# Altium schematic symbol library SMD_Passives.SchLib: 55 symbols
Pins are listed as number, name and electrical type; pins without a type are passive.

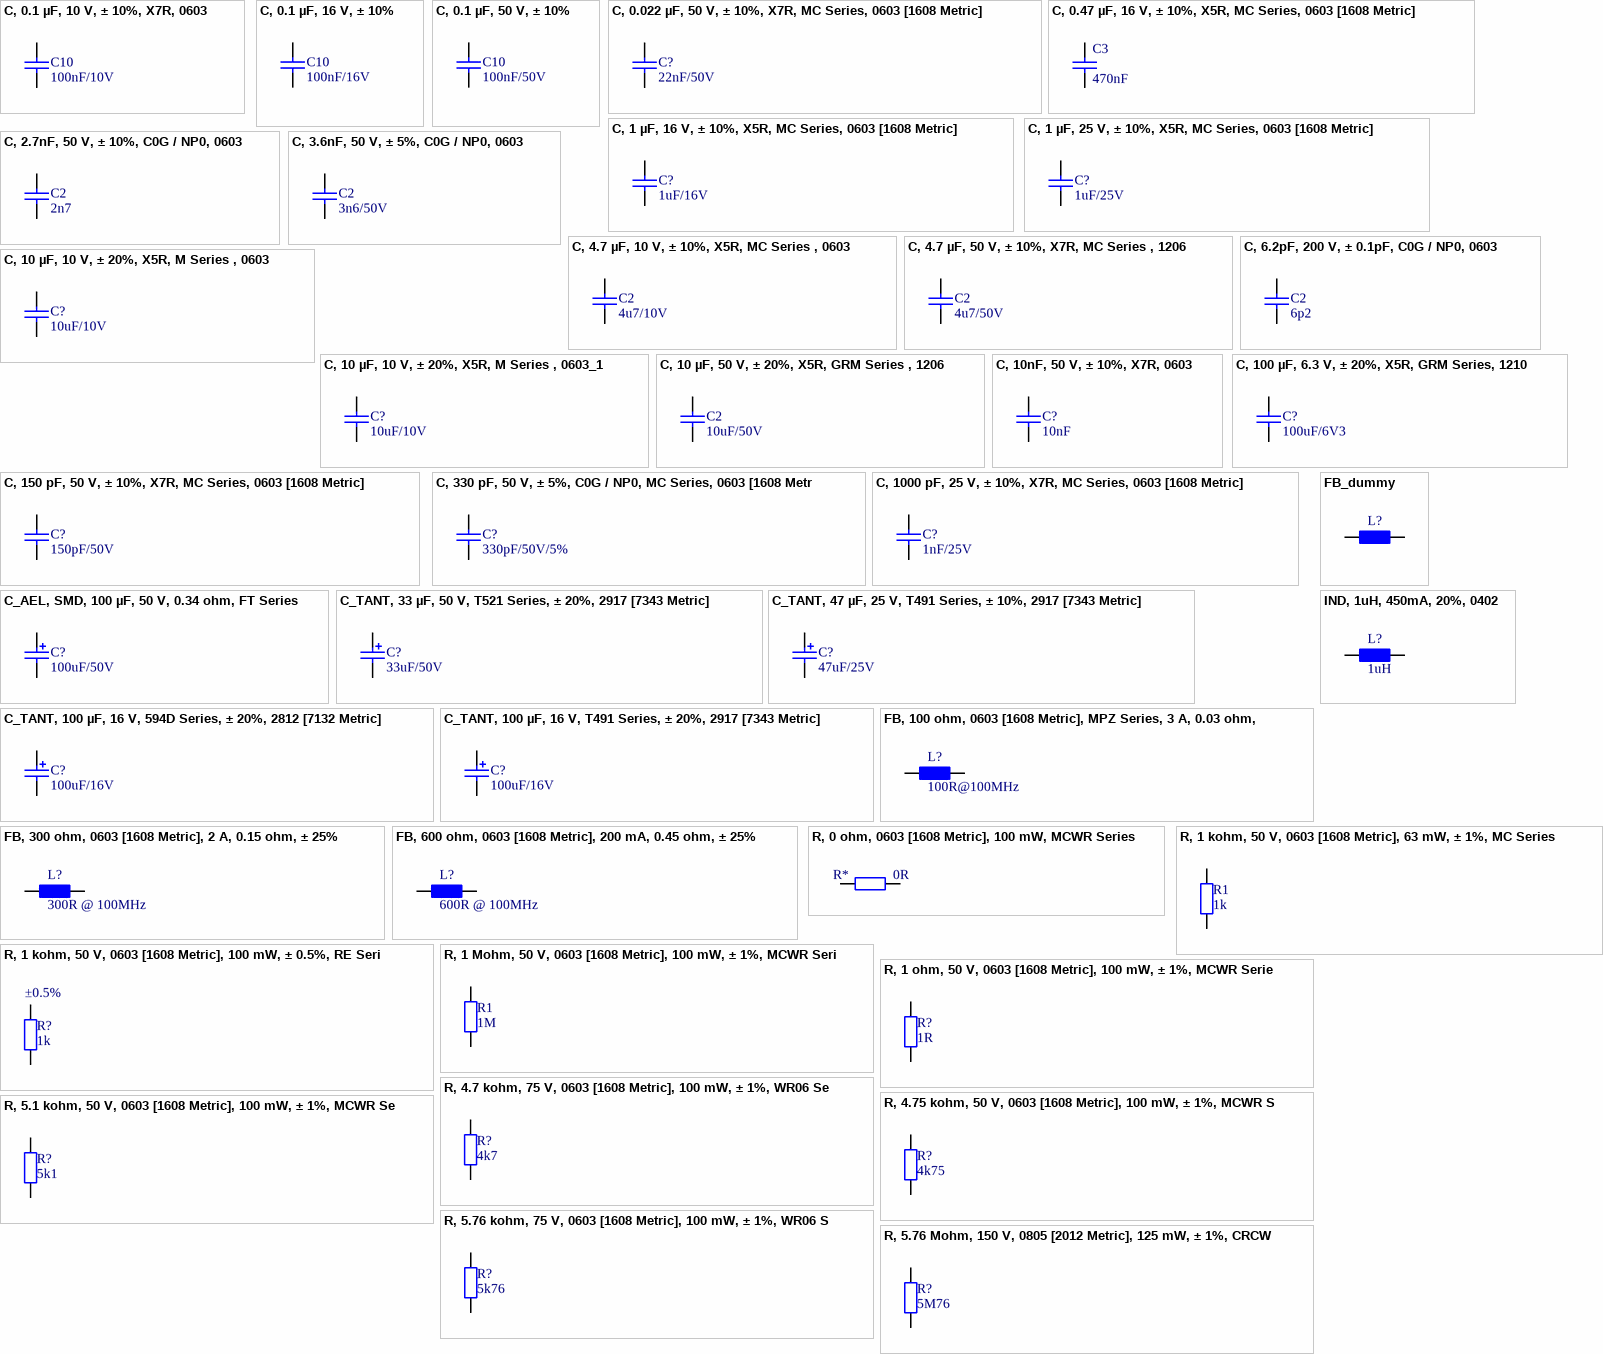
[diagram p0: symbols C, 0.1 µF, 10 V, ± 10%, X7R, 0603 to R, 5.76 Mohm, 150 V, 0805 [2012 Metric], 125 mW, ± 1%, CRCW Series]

## C, 0.1 µF, 10 V, ± 10%, X7R, 0603
designator C10, comment 100nF/10V
SMD Multilayer Ceramic Capacitor, 0603 [1608 Metric], 0.1 µF, 10 V, ± 10%, X7R, MC Series; MPN: MC0603B104K100CT; Type: MLCC; VoltageRating: 10V; MF: Multicomp; Capacitance: 100nF
footprint C0603 (0603 ceramic capacitor)
footprint C0603_BYPADD
footprint C0603_BYPASS
pins: 1, 2

## C, 0.1 µF, 16 V, ± 10%
designator C10, comment 100nF/16V
SMD Multilayer Ceramic Capacitor, 0603 [1608 Metric], 0.1 µF, 16 V, ± 10%, X7R, MC Series; MPN: MC0603B104K160CT; Type: MLCC; VoltageRating: 16V; ComponentLinknDescription: Datasheet; MF: Multicomp; Capacitance: 100nF
footprint C0603 (0603 ceramic capacitor)
footprint C0603_BYPADD
footprint C0603_BYPASS
pins: 1, 2

## C, 0.1 µF, 50 V, ± 10%
designator C10, comment 100nF/50V
SMD Multilayer Ceramic Capacitor, 0603 [1608 Metric], 0.1 µF, 50 V, ± 10%, X7R, MC Series; MPN: MC0603B104K500CT; Type: MLCC; VoltageRating: 50V; ComponentLinknDescription: Datasheet; MF: Multicomp; Capacitance: 100nF
footprint C0603 (0603 ceramic capacitor)
footprint C0603_BYPADD
footprint C0603_BYPASS
pins: 1, 2

## C, 0.022 µF, 50 V, ± 10%, X7R, MC Series, 0603 [1608 Metric]
designator C?, comment 22nF/50V
SMD Multilayer Ceramic Capacitor, 0603 [1608 Metric], 0.022 µF, 50 V, ± 10%, X7R, MC Series; MPN: MC0603B223K500CT; Type: MLCC; VoltageRating: 50V; MF: MULTICOMP; Capacitance: 22nF
footprint C0603 (0603 ceramic capacitor)
pins: 1, 2

## C, 0.47 µF, 16 V, ± 10%, X5R, MC Series, 0603 [1608 Metric]
designator C3, comment 470nF
SMD Multilayer Ceramic Capacitor, 0603 [1608 Metric], 0.47 µF, 16 V, ± 10%, X5R, MC Series; MPN: MC0603X474K160CT; Type: MLCC; Voltage rating: 16V; ComponentLinknDescription: Datasheet; MF: Multicomp
footprint C0603 (0603 ceramic capacitor)
pins: 1, 2

## C, 1 µF, 16 V, ± 10%, X5R, MC Series, 0603 [1608 Metric]
designator C?, comment 1uF/16V
SMD Multilayer Ceramic Capacitor, 0603 [1608 Metric], 1 µF, 16 V, ± 10%, X5R, MC Series; MPN: MC0603X105K160CT; Type: MLCC; VoltageRating: 16V; MF: MULTICOMP; Capacitance: 1uF
footprint C0603 (0603 ceramic capacitor)
pins: 1, 2

## C, 1 µF, 25 V, ± 10%, X5R, MC Series, 0603 [1608 Metric]
designator C?, comment 1uF/25V
SMD Multilayer Ceramic Capacitor, 0603 [1608 Metric], 1 µF, 25 V, ± 10%, X5R, MC Series; MPN: MC0603X105K250CT; Type: MLCC; VoltageRating: 25V; MF: MULTICOMP; Capacitance: 1uF
footprint C0603 (0603 ceramic capacitor)
pins: 1, 2

## C, 2.7nF, 50 V, ± 10%, C0G / NP0, 0603
designator C2, comment 2n7
SMD Multilayer Ceramic Capacitor, 0603 [1608 Metric], 2700 pF, 50 V, ± 10%, X7R, MC Series; MPN: MC0603B272K500CT; Type: MLCC; VoltageRating: 50V; MF: MULTICOMP
footprint C0603 (0603 ceramic capacitor)
pins: 1, 2

## C, 3.6nF, 50 V, ± 5%, C0G / NP0, 0603
designator C2, comment 3n6/50V
SMD Multilayer Ceramic Capacitor, 0603 [1608 Metric], 3600 pF, 50 V, ± 5%, C0G / NP0, C Series; MPN: C1608C0G1H151J080AA; Type: MLCC; VoltageRating: 50V; MF: TDK; Capacitance: 3n6
footprint C0603 (0603 ceramic capacitor)
pins: 1, 2

## C, 4.7 µF, 10 V, ± 10%, X5R, MC Series , 0603
designator C2, comment 4u7/10V
SMD Multilayer Ceramic Capacitor, 0603 [1608 Metric], 4.7 µF, 10 V, ± 10%, X5R, MC Series; MPN: MC0603X475K100CT; Type: MLCC; VoltageRating: 10V; MF: MULTICOMP; Capacitance: 4u7
footprint C0603 (Footprint not found)
pins: 1, 2

## C, 4.7 µF, 50 V, ± 10%, X7R, MC Series , 1206
designator C2, comment 4u7/50V
SMD Multilayer Ceramic Capacitor, 1206 [3216 Metric], 4.7 µF, 50 V, ± 10%, X7R, MC Series; MPN: MC1206B475K500CT; Type: MLCC; VoltageRating: 50V; MF: MULTICOMP; Capacitance: 4u7
footprint C1206 (1206 ceramic capacitor)
pins: 1, 2

## C, 6.2pF, 200 V, ± 0.1pF, C0G / NP0, 0603
designator C2, comment 6p2
Multilayer Ceramic Capacitors MLCC - SMD/SMT 200V 6.2pF C0G 0603 .1pF Tol; MPN: 06032U6R2BAT2A; Characteristic: C0G/NP0; MF: AVX; Precision: 0.1pF
footprint C0603 (0603 ceramic capacitor)
pins: 1, 2

## C, 10 µF, 10 V, ± 20%, X5R, M Series , 0603
designator C?, comment 10uF/10V
SMD Multilayer Ceramic Capacitor, 0603 [1608 Metric], 10 µF, 10 V, ± 20%, X5R, M Series; MPN: LMK107BBJ106MALT; Type: MLCC; VoltageRating: 10V; MF: TAIYO YUDEN; Capacitance: 10uF
footprint C0603 (0603 ceramic capacitor)
pins: 1, 2

## C, 10 µF, 10 V, ± 20%, X5R, M Series , 0603_1
designator C?, comment 10uF/10V
SMD Multilayer Ceramic Capacitor, 0603 [1608 Metric], 10 µF, 10 V, ± 20%, X5R, M Series; MPN: LMK107BBJ106MALT; Type: MLCC; VoltageRating: 10V; MF: TAIYO YUDEN; Capacitance: 10uF
footprint C0603 (0603 ceramic capacitor)
pins: 1, 2

## C, 10 µF, 50 V, ± 20%, X5R, GRM Series , 1206
designator C2, comment 10uF/50V
SMD Multilayer Ceramic Capacitor, 1206 [3216 Metric], 10 µF, 50 V, ± 20%, X5R, GRM Series; MPN: GRM31CR61H106MA12L; Type: MLCC; VoltageRating: 50V; MF: MURATA; Capacitance: 10uF
footprint C1206 (1206 ceramic capacitor)
pins: 1, 2

## C, 10nF, 50 V, ± 10%, X7R, 0603
designator C?, comment 10nF
SMD Multilayer Ceramic Capacitor, 0603 [1608 Metric], 0.01 µF, 50 V, ± 10%, X7R, MC Series; MPN: MC0603B103K500CT; Type: MLCC; VoltageRating: 50V; MF: MULTICOMP
footprint C0603 (0603 ceramic capacitor)
pins: 1, 2

## C, 100 µF, 6.3 V, ± 20%, X5R, GRM Series, 1210
designator C?, comment 100uF/6V3
SMD Multilayer Ceramic Capacitor, 1210 [3225 Metric], 100 µF, 6.3 V, ± 20%, X5R, GRM Series; MPN: GRM31CR60J107ME39L.; Type: MLCC; VoltageRating: 6V3; MF: MURATA; Capacitance: 100uF
footprint C1210 (1210 capacitor)
pins: 1, 2

## C, 150 pF, 50 V, ± 10%, X7R, MC Series, 0603 [1608 Metric]
designator C?, comment 150pF/50V
SMD Multilayer Ceramic Capacitor, 0603 [1608 Metric], 150 pF, 50 V, ± 10%, X7R, MC Series; MPN: MC0603B151K500CT; Type: MLCC; VoltageRating: 50V; MF: MULTICOMP; Capacitance: 150pF
footprint C0603 (0603 ceramic capacitor)
pins: 1, 2

## C, 330 pF, 50 V, ± 5%, C0G / NP0, MC Series, 0603 [1608 Metric]
designator C?, comment 330pF/50V/5%
SMD Multilayer Ceramic Capacitor, 0603 [1608 Metric], 330 pF, 50 V, ± 5%, C0G / NP0, MC Series; MPN: MC0603N331J500CT; Type: MLCC; VoltageRating: 50V; MF: MULTICOMP; Capacitance: 330pF
footprint C0603 (0603 ceramic capacitor)
pins: 1, 2

## C, 1000 pF, 25 V, ± 10%, X7R, MC Series, 0603 [1608 Metric]
designator C?, comment 1nF/25V
SMD Multilayer Ceramic Capacitor, 0603 [1608 Metric], 1000 pF, 25 V, ± 10%, X7R, MC Series; MPN: MC0603B102K250CT; Type: MLCC; VoltageRating: 25V; MF: MULTICOMP; Capacitance: 1nF
footprint C0603 (0603 ceramic capacitor)
pins: 1, 2

## C_AEL, SMD, 100 µF, 50 V, 0.34 ohm, FT Series
designator C?, comment 100uF/50V
SMD Aluminium Electrolytic Capacitor, Radial Can - SMD, 100 µF, 50 V, 0.34 ohm, FT Series; MPN: EEEFTH101XAP; Type: MLCC; VoltageRating: 50V; MF: PANASONIC ELECTRONIC COMPONENTS; Capacitance: 100uF
footprint EEEFTH101XAP (Aluminum Electrolytic Capacitor, Body 6,60x6,60x8,00mm, IPC High Density)
pins: 1, 2

## C_TANT, 33 µF, 50 V, T521 Series, ± 20%, 2917 [7343 Metric]
designator C?, comment 33uF/50V
Surface Mount Tantalum Capacitor, 33 µF, 50 V, T521 Series, ± 20%, 2917 [7343 Metric]; MPN: T521X336M050ATE075; Type: MLCC; VoltageRating: 50V; MF: KEMET; Capacitance: 33uF
footprint TAN_X/E (Capacitor, SM Tantalum; Body 7.3 x 4.3 mm (LxW typ))
pins: 1, 2

## C_TANT, 47 µF, 25 V, T491 Series, ± 10%, 2917 [7343 Metric]
designator C?, comment 47uF/25V
Surface Mount Tantalum Capacitor, 47 µF, 25 V, T491 Series, ± 10%, 2917 [7343 Metric]; MPN: T491X476K025AT; Type: TANTAL; VoltageRating: 25V; MF: KEMET; Capacitance: 47uF
footprint TAN_X/E (Capacitor, SM Tantalum; Body 7.3 x 4.3 mm (LxW typ))
pins: 1, 2

## C_TANT, 100 µF, 16 V, 594D Series, ± 20%, 2812 [7132 Metric]
designator C?, comment 100uF/16V
Surface Mount Tantalum Capacitor, TANTAMOUNT®, 100 µF, 16 V, 594D Series, ± 20%, 2812 [7132 Metric]; MPN: 594D107X0016C2T; VoltageRating: 16V; MF: VISHAY; Capacitance: 100uF
footprint C_TANT_594D Series_CASE_C
pins: 1, 2

## C_TANT, 100 µF, 16 V, T491 Series, ± 20%, 2917 [7343 Metric]
designator C?, comment 100uF/16V
Surface Mount Tantalum Capacitor, 100 µF, 16 V, T491 Series, ± 20%, 2917 [7343 Metric]; MPN: T491D107M016AT; Type: MLCC; VoltageRating: 16V; Characteristic: X5R; MF: KEMET; Capacitance: 100uF
footprint TAN_V/Y_D (Capacitor, SM Tantalum; Body 7.3 x 4.3 mm (LxW typ))
pins: 1, 2

## FB, 100 ohm, 0603 [1608 Metric], MPZ Series, 3 A, 0.03 ohm, ± 25%
designator L?, comment 100R@100MHz
Ferrite Bead, 100 ohm, 0603 [1608 Metric], MPZ Series, 3 A, 0.03 ohm, ± 25%; MPN: MPZ1608S101A; MF: TDK; DC Current Rating: 3A; DC Resistance Max:: 0.03R
footprint L0603 (0603 inductor)
footprint L0402 (0402 inductor)
pins: 1, 2

## FB, 300 ohm, 0603 [1608 Metric], 2 A, 0.15 ohm, ± 25%
designator L?, comment 300R @ 100MHz
Ferrite Bead, 300 ohm, 0603 [1608 Metric], 2 A, 0.15 ohm, ± 25%; MPN: 742792641; MF: WURTH ELEKTRONIK; DC Current Rating: 2A; DC Resistance Max:: 0R15
footprint L0603 (0603 inductor)
pins: 1, 2

## FB, 600 ohm, 0603 [1608 Metric], 200 mA, 0.45 ohm, ± 25%
designator L?, comment 600R @ 100MHz
Ferrite Bead, 600 ohm, 0603 [1608 Metric], 200 mA, 0.45 ohm, ± 25%; MPN: 74279265; MF: WURTH ELEKTRONIK; DC Current Rating: 200mA; DC Resistance Max:: 0R45
footprint L0603 (0603 inductor)
pins: 1, 2

## FB_dummy
designator L?
footprint L0603 (0603 inductor)
footprint L0402 (0402 inductor)
pins: 1, 2

## IND, 1uH, 450mA, 20%, 0402
designator L?, comment 1uH
Fixed Inductors 1 UH 20%; MPN: MLZ1005M1R0WT000; MF: TDK; DC Current Rating: 450mA; DC Resistance Max:: 0R35
footprint L0402 (0402 inductor)
pins: 1, 2

## R, 0 ohm, 0603 [1608 Metric], 100 mW, MCWR Series
designator R*, comment 0R
SMD Chip Resistor, Thick Film, 0 ohm, 0603 [1608 Metric], 100 mW, MCWR Series; MPN: MCWR06X000 PTL; Temp coefficient: *ppm; PowerRating: 100mW; MF: MULTICOMP
footprint R0402 (0402 resistor)
footprint R0603 (0603 resistor)
footprint R0805 (0805 resistor)
footprint R1206 (1206 resistor)
footprint R2512 (2512 resistor)
footprint R0201 (0201 resistor)
footprint R1210 (1210 resistor)
footprint R1812 (1812 resistor)
footprint R2010 (2010 resistor)
footprint R2512 (2512 resistor)
pins: 1, 2

## R, 1 kohm, 50 V, 0603 [1608 Metric], 63 mW, ± 1%, MC Series
designator R1, comment 1k
SMD Chip Resistor, Thick Film, 1 kohm, 50 V, 0603 [1608 Metric], 100 mW, ± 0.5%, RE Series; MPN: MC0063W060311K; Precision: 1%; VoltageRating: 50V; Temp coefficient: *ppm; PowerRating: 63mW; MF: MULTICOMP
footprint R0603 (0603 resistor)
pins: 1, 2

## R, 1 kohm, 50 V, 0603 [1608 Metric], 100 mW, ± 0.5%, RE Series
designator R?, comment Precision: ±0.5%  (hidden comment: 1k)
SMD Chip Resistor, Thick Film, 1 kohm, 50 V, 0603 [1608 Metric], 100 mW, ± 0.5%, RE Series; MPN: RE0603DR-071KL; VoltageRating: 50V; Temp coefficient: *ppm; PowerRating: 100mW; MF: YAGEO (PHYCOMP)
footprint R0402 (0402 resistor)
footprint R0603 (0603 resistor)
footprint R0805 (0805 resistor)
footprint R1206 (1206 resistor)
footprint R2512 (2512 resistor)
footprint R0201 (0201 resistor)
footprint R1210 (1210 resistor)
footprint R1812 (1812 resistor)
footprint R2010 (2010 resistor)
footprint R2512 (2512 resistor)
pins: 1, 2

## R, 1 Mohm, 50 V, 0603 [1608 Metric], 100 mW, ± 1%, MCWR Series
designator R1, comment 1M
SMD Chip Resistor, Thick Film, 1 Mohm, 50 V, 0603 [1608 Metric], 100 mW, ± 1%, MCWR Series; MPN: MCWR06X1004FTL; VoltageRating: 50V; Temp coefficient: *ppm; PowerRating: 100mW; MF: MULTICOMP
footprint R0603 (0603 resistor)
pins: 1, 2

## R, 1 ohm, 50 V, 0603 [1608 Metric], 100 mW, ± 1%, MCWR Series
designator R?, comment 1R
SMD Chip Resistor, Thick Film, 1 ohm, 50 V, 0603 [1608 Metric], 100 mW, ± 1%, MCWR Series; MPN: MCWR06W1R00FTL; VoltageRating: 50V; Temp coefficient: *ppm; PowerRating: 100mW; MF: MULTICOMP
footprint R0402 (0402 resistor)
footprint R0603 (0603 resistor)
footprint R0805 (0805 resistor)
footprint R1206 (1206 resistor)
footprint R2512 (2512 resistor)
footprint R0201 (0201 resistor)
footprint R1210 (1210 resistor)
footprint R1812 (1812 resistor)
footprint R2010 (2010 resistor)
footprint R2512 (2512 resistor)
pins: 1, 2

## R, 4.7 kohm, 75 V, 0603 [1608 Metric], 100 mW, ± 1%, WR06 Series
designator R?, comment 4k7
SMD Chip Resistor, 4.7 kohm, 75 V, 0603 [1608 Metric], 100 mW, ± 1%, WR06 Series; MPN: WR06X4701FTL; VoltageRating: 75V; Temp coefficient: *ppm; PowerRating: 100mW; MF: WALSIN
footprint R0402 (0402 resistor)
footprint R0603 (0603 resistor)
footprint R0805 (0805 resistor)
footprint R1206 (1206 resistor)
footprint R2512 (2512 resistor)
footprint R0201 (0201 resistor)
footprint R1210 (1210 resistor)
footprint R1812 (1812 resistor)
footprint R2010 (2010 resistor)
footprint R2512 (2512 resistor)
pins: 1, 2

## R, 4.75 kohm, 50 V, 0603 [1608 Metric], 100 mW, ± 1%, MCWR Series
designator R?, comment 4k75
SMD Chip Resistor, Thick Film, 4.75 kohm, 50 V, 0603 [1608 Metric], 100 mW, ± 1%, MCWR Series; MPN: MCWR06X4751FTL; VoltageRating: 50V; Temp coefficient: *ppm; PowerRating: 100mW; MF: MULTICOMP
footprint R0402 (0402 resistor)
footprint R0603 (0603 resistor)
footprint R0805 (0805 resistor)
footprint R1206 (1206 resistor)
footprint R2512 (2512 resistor)
footprint R0201 (0201 resistor)
footprint R1210 (1210 resistor)
footprint R1812 (1812 resistor)
footprint R2010 (2010 resistor)
footprint R2512 (2512 resistor)
pins: 1, 2

## R, 5.1 kohm, 50 V, 0603 [1608 Metric], 100 mW, ± 1%, MCWR Series
designator R?, comment 5k1
SMD Chip Resistor, Thick Film, 5.1 kohm, 50 V, 0603 [1608 Metric], 100 mW, ± 1%, MCWR Series; MPN: MCWR06X5101FTL; VoltageRating: 50V; Temp coefficient: *ppm; PowerRating: 100mW; MF: MULTICOMP
footprint R0402 (0402 resistor)
footprint R0603 (0603 resistor)
footprint R0805 (0805 resistor)
footprint R1206 (1206 resistor)
footprint R2512 (2512 resistor)
footprint R0201 (0201 resistor)
footprint R1210 (1210 resistor)
footprint R1812 (1812 resistor)
footprint R2010 (2010 resistor)
footprint R2512 (2512 resistor)
pins: 1, 2

## R, 5.76 kohm, 75 V, 0603 [1608 Metric], 100 mW, ± 1%, WR06 Series
designator R?, comment 5k76
SMD Chip Resistor, 5.76 kohm, 75 V, 0603 [1608 Metric], 100 mW, ± 1%, WR06 Series; MPN: WR06X5761FTL; VoltageRating: 75V; Temp coefficient: *ppm; PowerRating: 100mW; MF: WALSIN
footprint R0402 (0402 resistor)
footprint R0603 (0603 resistor)
footprint R0805 (0805 resistor)
footprint R1206 (1206 resistor)
footprint R2512 (2512 resistor)
footprint R0201 (0201 resistor)
footprint R1210 (1210 resistor)
footprint R1812 (1812 resistor)
footprint R2010 (2010 resistor)
footprint R2512 (2512 resistor)
pins: 1, 2

## R, 5.76 Mohm, 150 V, 0805 [2012 Metric], 125 mW, ± 1%, CRCW Series
designator R?, comment 5M76
SMD Chip Resistor, Thick Film, 5.76 Mohm, 150 V, 0805 [2012 Metric], 125 mW, ± 1%, CRCW Series; MPN: CRCW08055M76FKEA; VoltageRating: 150V; Temp coefficient: *ppm; PowerRating: 125mW; MF: VISHAY
footprint R0402 (0402 resistor)
footprint R0603 (0603 resistor)
footprint R0805 (0805 resistor)
footprint R1206 (1206 resistor)
footprint R2512 (2512 resistor)
footprint R0201 (0201 resistor)
footprint R1210 (1210 resistor)
footprint R1812 (1812 resistor)
footprint R2010 (2010 resistor)
footprint R2512 (2512 resistor)
pins: 1, 2

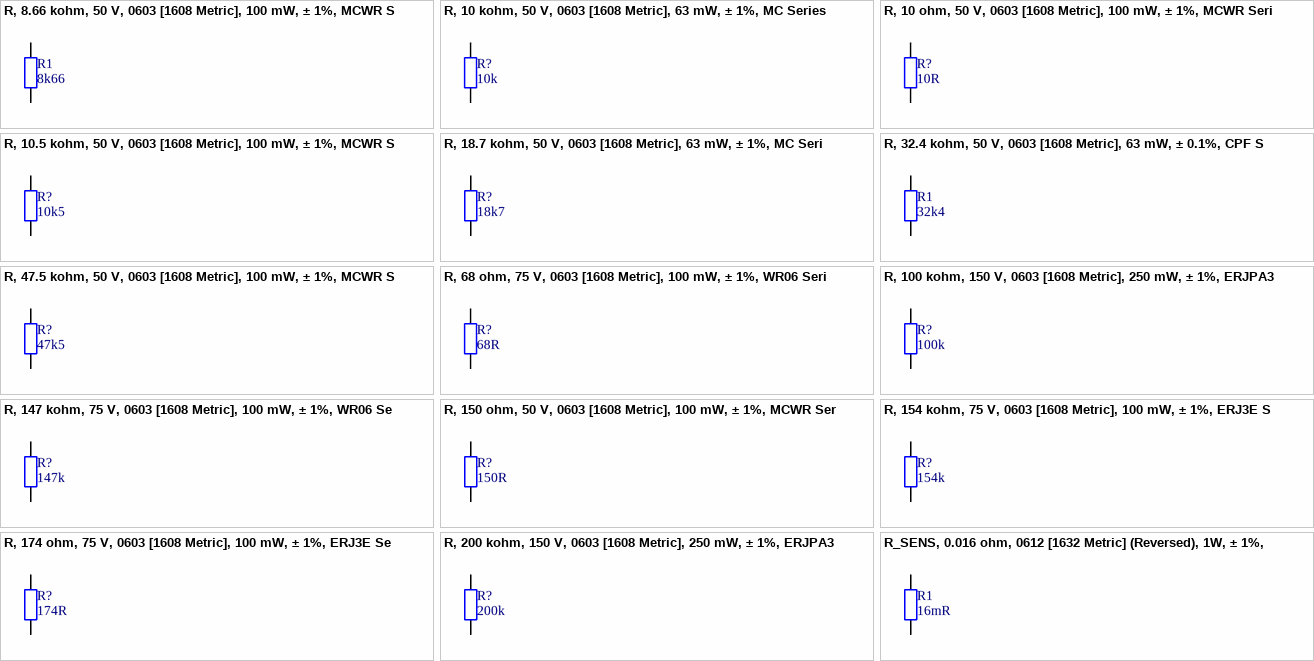
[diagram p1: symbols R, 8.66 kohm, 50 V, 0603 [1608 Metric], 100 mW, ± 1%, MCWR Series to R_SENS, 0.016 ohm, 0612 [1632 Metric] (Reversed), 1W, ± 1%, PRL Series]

## R, 8.66 kohm, 50 V, 0603 [1608 Metric], 100 mW, ± 1%, MCWR Series
designator R1, comment 8k66
SMD Chip Resistor, Thick Film, 8.66 kohm, 50 V, 0603 [1608 Metric], 100 mW, ± 1%, MCWR Series; MPN: MCWR06X8661FTL; VoltageRating: 50V; Temp coefficient: *ppm; PowerRating: 100mW; MF: MULTICOMP
footprint R0603 (0603 resistor)
pins: 1, 2

## R, 10 kohm, 50 V, 0603 [1608 Metric], 63 mW, ± 1%, MC Series
designator R?, comment 10k
SMD Chip Resistor, Thick Film, 10 kohm, 50 V, 0603 [1608 Metric], 63 mW, ± 1%, MC Series; MPN: MC0063W0603110K; VoltageRating: 50V; Temp coefficient: *ppm; PowerRating: 63mW; MF: MULTICOMP
footprint R0402 (0402 resistor)
footprint R0603 (0603 resistor)
footprint R0805 (0805 resistor)
footprint R1206 (1206 resistor)
footprint R2512 (2512 resistor)
footprint R0201 (0201 resistor)
footprint R1210 (1210 resistor)
footprint R1812 (1812 resistor)
footprint R2010 (2010 resistor)
footprint R2512 (2512 resistor)
pins: 1, 2

## R, 10 ohm, 50 V, 0603 [1608 Metric], 100 mW, ± 1%, MCWR Series
designator R?, comment 10R
SMD Chip Resistor, Thick Film, 10 ohm, 50 V, 0603 [1608 Metric], 100 mW, ± 1%, MCWR Series; MPN: MC0063W0603110K; VoltageRating: 50V; Temp coefficient: *ppm; PowerRating: 100mW; MF: MULTICOMP
footprint R0402 (0402 resistor)
footprint R0603 (0603 resistor)
footprint R0805 (0805 resistor)
footprint R1206 (1206 resistor)
footprint R2512 (2512 resistor)
footprint R0201 (0201 resistor)
footprint R1210 (1210 resistor)
footprint R1812 (1812 resistor)
footprint R2010 (2010 resistor)
footprint R2512 (2512 resistor)
pins: 1, 2

## R, 10.5 kohm, 50 V, 0603 [1608 Metric], 100 mW, ± 1%, MCWR Series
designator R?, comment 10k5
SMD Chip Resistor, Thick Film, 10.5 kohm, 50 V, 0603 [1608 Metric], 100 mW, ± 1%, MCWR Series; MPN: MCWR06X1052FTL; VoltageRating: 50V; Temp coefficient: *ppm; PowerRating: 100mW; MF: MULTICOMP
footprint R0402 (0402 resistor)
footprint R0603 (0603 resistor)
footprint R0805 (0805 resistor)
footprint R1206 (1206 resistor)
footprint R2512 (2512 resistor)
footprint R0201 (0201 resistor)
footprint R1210 (1210 resistor)
footprint R1812 (1812 resistor)
footprint R2010 (2010 resistor)
footprint R2512 (2512 resistor)
pins: 1, 2

## R, 18.7 kohm, 50 V, 0603 [1608 Metric], 63 mW, ± 1%, MC Series
designator R?, comment 18k7
SMD Chip Resistor, Thick Film, 18.7 kohm, 50 V, 0603 [1608 Metric], 63 mW, ± 1%, MC Series; MPN: MC0063W0603118K7; VoltageRating: 50V; Temp coefficient: *ppm; PowerRating: 100mW; MF: MULTICOMP
footprint R0402 (0402 resistor)
footprint R0603 (0603 resistor)
footprint R0805 (0805 resistor)
footprint R1206 (1206 resistor)
footprint R2512 (2512 resistor)
footprint R0201 (0201 resistor)
footprint R1210 (1210 resistor)
footprint R1812 (1812 resistor)
footprint R2010 (2010 resistor)
footprint R2512 (2512 resistor)
pins: 1, 2

## R, 32.4 kohm, 50 V, 0603 [1608 Metric], 63 mW, ± 0.1%, CPF Series
designator R1, comment 32k4
SMD Chip Resistor, Thin Film, 32.4 kohm, 50 V, 0603 [1608 Metric], 63 mW, ± 0.1%, CPF Series; MPN: CPF0603B32K4E1; Precision: 1%; VoltageRating: 50V; Temp coefficient: *ppm; PowerRating: 63mW; MF: TE CONNECTIVITY
footprint R0603 (0603 resistor)
pins: 1, 2

## R, 47.5 kohm, 50 V, 0603 [1608 Metric], 100 mW, ± 1%, MCWR Series
designator R?, comment 47k5
SMD Chip Resistor, Thick Film, 47.5 kohm, 50 V, 0603 [1608 Metric], 100 mW, ± 1%, MCWR Series; MPN: MCWR06X4752FTL; VoltageRating: 50V; Temp coefficient: *ppm; PowerRating: 100mW; MF: MULTICOMP
footprint R0402 (0402 resistor)
footprint R0603 (0603 resistor)
footprint R0805 (0805 resistor)
footprint R1206 (1206 resistor)
footprint R2512 (2512 resistor)
footprint R0201 (0201 resistor)
footprint R1210 (1210 resistor)
footprint R1812 (1812 resistor)
footprint R2010 (2010 resistor)
footprint R2512 (2512 resistor)
pins: 1, 2

## R, 68 ohm, 75 V, 0603 [1608 Metric], 100 mW, ± 1%, WR06 Series
designator R?, comment 68R
SMD Chip Resistor, 68 ohm, 75 V, 0603 [1608 Metric], 100 mW, ± 1%, WR06 Series; MPN: WR06X68R0FTL; VoltageRating: 75V; Temp coefficient: *ppm; PowerRating: 100mW; MF: WALSIN
footprint R0402 (0402 resistor)
footprint R0603 (0603 resistor)
footprint R0805 (0805 resistor)
footprint R1206 (1206 resistor)
footprint R2512 (2512 resistor)
footprint R0201 (0201 resistor)
footprint R1210 (1210 resistor)
footprint R1812 (1812 resistor)
footprint R2010 (2010 resistor)
footprint R2512 (2512 resistor)
pins: 1, 2

## R, 100 kohm, 150 V, 0603 [1608 Metric], 250 mW, ± 1%, ERJPA3 Series
designator R?, comment 100k
SMD Chip Resistor, Thick Film, 100 kohm, 150 V, 0603 [1608 Metric], 250 mW, ± 1%, ERJPA3 Series; MPN: ERJPA3F1003V; VoltageRating: 150V; Temp coefficient: *ppm; PowerRating: 250mW; MF: PANASONIC ELECTRONIC COMPONENTS
footprint R0402 (0402 resistor)
footprint R0603 (0603 resistor)
footprint R0805 (0805 resistor)
footprint R1206 (1206 resistor)
footprint R2512 (2512 resistor)
footprint R0201 (0201 resistor)
footprint R1210 (1210 resistor)
footprint R1812 (1812 resistor)
footprint R2010 (2010 resistor)
footprint R2512 (2512 resistor)
pins: 1, 2

## R, 147 kohm, 75 V, 0603 [1608 Metric], 100 mW, ± 1%, WR06 Series
designator R?, comment 147k
SMD Chip Resistor, 147 kohm, 75 V, 0603 [1608 Metric], 100 mW, ± 1%, WR06 Series; MPN: WR06X1473FTL; VoltageRating: 75V; Temp coefficient: *ppm; PowerRating: 100mW; MF: WALSIN
footprint R0402 (0402 resistor)
footprint R0603 (0603 resistor)
footprint R0805 (0805 resistor)
footprint R1206 (1206 resistor)
footprint R2512 (2512 resistor)
footprint R0201 (0201 resistor)
footprint R1210 (1210 resistor)
footprint R1812 (1812 resistor)
footprint R2010 (2010 resistor)
footprint R2512 (2512 resistor)
pins: 1, 2

## R, 150 ohm, 50 V, 0603 [1608 Metric], 100 mW, ± 1%, MCWR Series
designator R?, comment 150R
SMD Chip Resistor, Thick Film, 150 ohm, 50 V, 0603 [1608 Metric], 100 mW, ± 1%, MCWR Series; MPN: MCWR06X1500FTL; VoltageRating: 50V; Temp coefficient: *ppm; PowerRating: 100mW; MF: MULTICOMP
footprint R0402 (0402 resistor)
footprint R0603 (0603 resistor)
footprint R0805 (0805 resistor)
footprint R1206 (1206 resistor)
footprint R2512 (2512 resistor)
footprint R0201 (0201 resistor)
footprint R1210 (1210 resistor)
footprint R1812 (1812 resistor)
footprint R2010 (2010 resistor)
footprint R2512 (2512 resistor)
pins: 1, 2

## R, 154 kohm, 75 V, 0603 [1608 Metric], 100 mW, ± 1%, ERJ3E Series
designator R?, comment 154k
SMD Chip Resistor, Thick Film, 154 kohm, 75 V, 0603 [1608 Metric], 100 mW, ± 1%, ERJ3E Series; MPN: ERJ3EKF1543V; VoltageRating: 75V; Temp coefficient: *ppm; PowerRating: 100mW; MF: PANASONIC ELECTRONIC COMPONENTS
footprint R0402 (0402 resistor)
footprint R0603 (0603 resistor)
footprint R0805 (0805 resistor)
footprint R1206 (1206 resistor)
footprint R2512 (2512 resistor)
footprint R0201 (0201 resistor)
footprint R1210 (1210 resistor)
footprint R1812 (1812 resistor)
footprint R2010 (2010 resistor)
footprint R2512 (2512 resistor)
pins: 1, 2

## R, 174 ohm, 75 V, 0603 [1608 Metric], 100 mW, ± 1%, ERJ3E Series
designator R?, comment 174R
SMD Chip Resistor, Thick Film, 10 ohm, 50 V, 0603 [1608 Metric], 100 mW, ± 1%, MCWR Series; MPN: ERJ3EKF1740V; VoltageRating: 75V; Temp coefficient: *ppm; PowerRating: 100mW; MF: PANASONIC ELECTRONIC COMPONENTS
footprint R0402 (0402 resistor)
footprint R0603 (0603 resistor)
footprint R0805 (0805 resistor)
footprint R1206 (1206 resistor)
footprint R2512 (2512 resistor)
footprint R0201 (0201 resistor)
footprint R1210 (1210 resistor)
footprint R1812 (1812 resistor)
footprint R2010 (2010 resistor)
footprint R2512 (2512 resistor)
pins: 1, 2

## R, 200 kohm, 150 V, 0603 [1608 Metric], 250 mW, ± 1%, ERJPA3 Series
designator R?, comment 200k
SMD Chip Resistor, Thick Film, 200 kohm, 150 V, 0603 [1608 Metric], 250 mW, ± 1%, ERJPA3 Series; MPN: ERJPA3F2003V; VoltageRating: 150V; Temp coefficient: *ppm; PowerRating: 250mW; MF: PANASONIC ELECTRONIC COMPONENTS
footprint R0402 (0402 resistor)
footprint R0603 (0603 resistor)
footprint R0805 (0805 resistor)
footprint R1206 (1206 resistor)
footprint R2512 (2512 resistor)
footprint R0201 (0201 resistor)
footprint R1210 (1210 resistor)
footprint R1812 (1812 resistor)
footprint R2010 (2010 resistor)
footprint R2512 (2512 resistor)
pins: 1, 2

## R_SENS, 0.016 ohm, 0612 [1632 Metric] (Reversed), 1W, ± 1%, PRL Series
designator R1, comment 16mR
SMD Chip Resistor, Thick Film, Current Sense Resistors - SMD 1W 0.016ohm 1%; MPN: MCWR06X1004FTL; VoltageRating: 50V; Temp coefficient: *ppm; MF: MULTICOMP
footprint 0612 (Reversed) (Chip Resistor, 2-Leads, Body 1,60x3,20mm, IPC Medium Density)
pins: 1, 2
